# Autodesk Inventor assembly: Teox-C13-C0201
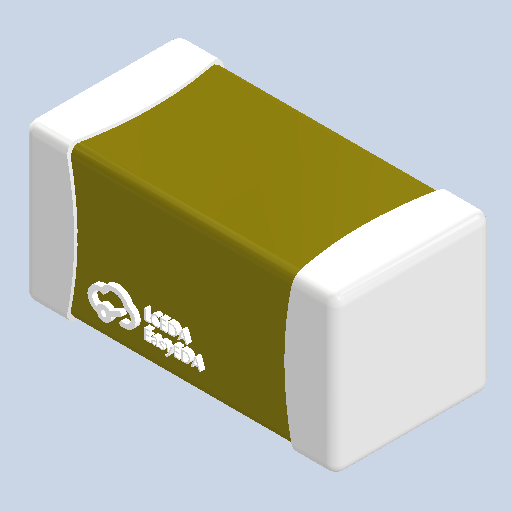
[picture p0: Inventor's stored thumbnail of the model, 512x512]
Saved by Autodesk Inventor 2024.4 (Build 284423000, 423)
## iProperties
Created: 2025-05
Part Number: Teox-C13-C0201
Document SubType Name: Assembly
Designer: AdminForWorker
Title: Teox-C13-C0201
Author: AdminForWorker
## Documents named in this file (2)
- c:\worker\convert-fusion-r02-cosv3\tmp\job-1\2\temp\files\be827049-a7f2-47ea-a815-8d9efd6bfce9\Teox-C13-C0201.iam
- c:\worker\convert-fusion-r02-cosv3\tmp\job-1\2\temp\files\be827049-a7f2-47ea-a815-8d9efd6bfce9\COMPOUND (3).ipt
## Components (1 placed, 1 different names)
1. COMPOUND (3):8
